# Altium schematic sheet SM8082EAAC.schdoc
size 127 x 101 mm
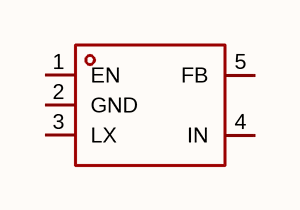
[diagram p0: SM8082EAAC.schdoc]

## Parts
U?  sm8082eaac  [SOT-23-5_L2.9-W1.6-P0.95-LS2.8-BR]  (value not drawn)

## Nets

Not connected (* = marked no-connect by the designer): U? 1(EN) 2(GND) 3(LX) 4(IN) 5(FB)

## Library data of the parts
U? = sm8082eaac: 功能类型:降压型;工作电压:2.5V~5.5V;输出电压:-;输出电流:2A;输出类型:固定;; Manufacturer: Silergy(矽力杰); AddInBom: yes; ModelId: 7ba65df16e7b4570af156e925f9c37fe; ModelTransform: 114.173,114.173,0,90,0,0,0,0,0; Function: 降压型; Output Current: 2A; Frequency - Switching: 1.5MHz; Synchronous Rectifier: 是; Number of Outputs: 1; Topology: 降压式; Quiescent Current: 100uA; Switch tube (built-in/external): 内置; Output Type: 固定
